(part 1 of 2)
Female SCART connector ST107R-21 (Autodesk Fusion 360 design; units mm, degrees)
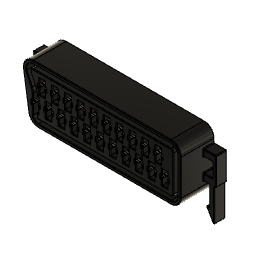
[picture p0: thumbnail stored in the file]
sketch "Sketch1" plane through (0, 0, 0) normal (0, 1, 0) x axis (1, 0, 0)
  line L1 (47.1, 0) -> (0, 0)
  line L2 (47.1, -16.5) -> (47.1, 0)
  line L3 (0, -16.5) -> (47.1, -16.5)
  line L4 (0, 0) -> (0, -16.5)
  line L5 (0, -8.25) -> (47.1, -8.25)
  line L6 (0, -5.71) -> (47.1, -5.71)
  line L7 (0, -10.79) -> (47.1, -10.79)
  line L8 (23.3, -16.5) -> (23.3, 0)
  line L9 (24.1, -7.81) -> (22.5, -7.81)
  line L10 (24.1, -3.61) -> (24.1, -7.81)
  line L11 (22.5, -3.61) -> (24.1, -3.61)
  line L12 (22.5, -7.81) -> (22.5, -3.61)
  line L13 (3.45, -3.61) -> (5.05, -3.61)
  line L14 (5.05, -3.61) -> (5.05, -7.81)
  line L15 (3.45, -7.81) -> (3.45, -3.61)
  line L16 (5.05, -7.81) -> (3.45, -7.81)
  line L17 (7.26, -3.61) -> (8.86, -3.61)
  line L18 (8.86, -3.61) -> (8.86, -7.81)
  line L19 (7.26, -7.81) -> (7.26, -3.61)
  line L20 (8.86, -7.81) -> (7.26, -7.81)
  line L21 (11.07, -3.61) -> (12.67, -3.61)
  line L22 (12.67, -3.61) -> (12.67, -7.81)
  line L23 (11.07, -7.81) -> (11.07, -3.61)
  line L24 (12.67, -7.81) -> (11.07, -7.81)
  line L25 (14.88, -3.61) -> (16.48, -3.61)
  line L26 (16.48, -3.61) -> (16.48, -7.81)
  line L27 (14.88, -7.81) -> (14.88, -3.61)
  line L28 (16.48, -7.81) -> (14.88, -7.81)
  line L29 (18.69, -3.61) -> (20.29, -3.61)
  line L30 (20.29, -3.61) -> (20.29, -7.81)
  line L31 (18.69, -7.81) -> (18.69, -3.61)
  line L32 (20.29, -7.81) -> (18.69, -7.81)
  line L33 (26.31, -3.61) -> (27.91, -3.61)
  line L34 (27.91, -3.61) -> (27.91, -7.81)
  line L35 (26.31, -7.81) -> (26.31, -3.61)
  line L36 (27.91, -7.81) -> (26.31, -7.81)
  line L37 (30.12, -3.61) -> (31.72, -3.61)
  line L38 (31.72, -3.61) -> (31.72, -7.81)
  line L39 (30.12, -7.81) -> (30.12, -3.61)
  line L40 (31.72, -7.81) -> (30.12, -7.81)
  line L41 (33.93, -3.61) -> (35.53, -3.61)
  line L42 (35.53, -3.61) -> (35.53, -7.81)
  line L43 (33.93, -7.81) -> (33.93, -3.61)
  line L44 (35.53, -7.81) -> (33.93, -7.81)
  line L45 (37.74, -3.61) -> (39.34, -3.61)
  line L46 (39.34, -3.61) -> (39.34, -7.81)
  line L47 (37.74, -7.81) -> (37.74, -3.61)
  line L48 (39.34, -7.81) -> (37.74, -7.81)
  line L49 (41.55, -3.61) -> (43.15, -3.61)
  line L50 (43.15, -3.61) -> (43.15, -7.81)
  line L51 (41.55, -7.81) -> (41.55, -3.61)
  line L52 (43.15, -7.81) -> (41.55, -7.81)
  line L53 (41.55, -7.81) -> (39.34, -7.81)
  line L54 (40.445, -14) -> (40.445, -7.81)
  line L55 (41.245, -12.89) -> (39.645, -12.89)
  line L56 (41.245, -8.69) -> (41.245, -12.89)
  line L57 (39.645, -8.69) -> (41.245, -8.69)
  line L58 (39.645, -12.89) -> (39.645, -8.69)
  line L59 (37.435, -8.69) -> (37.435, -12.89)
  line L60 (35.835, -8.69) -> (37.435, -8.69)
  line L61 (35.835, -12.89) -> (35.835, -8.69)
  line L62 (37.435, -12.89) -> (35.835, -12.89)
  line L63 (33.625, -8.69) -> (33.625, -12.89)
  line L64 (32.025, -8.69) -> (33.625, -8.69)
  line L65 (32.025, -12.89) -> (32.025, -8.69)
  line L66 (33.625, -12.89) -> (32.025, -12.89)
  line L67 (29.815, -8.69) -> (29.815, -12.89)
  line L68 (28.215, -8.69) -> (29.815, -8.69)
  line L69 (28.215, -12.89) -> (28.215, -8.69)
  line L70 (29.815, -12.89) -> (28.215, -12.89)
  line L71 (26.005, -8.69) -> (26.005, -12.89)
  line L72 (24.405, -8.69) -> (26.005, -8.69)
  line L73 (24.405, -12.89) -> (24.405, -8.69)
  line L74 (26.005, -12.89) -> (24.405, -12.89)
  line L75 (22.195, -8.69) -> (22.195, -12.89)
  line L76 (20.595, -8.69) -> (22.195, -8.69)
  line L77 (20.595, -12.89) -> (20.595, -8.69)
  line L78 (22.195, -12.89) -> (20.595, -12.89)
  line L79 (18.385, -8.69) -> (18.385, -12.89)
  line L80 (16.785, -8.69) -> (18.385, -8.69)
  line L81 (16.785, -12.89) -> (16.785, -8.69)
  line L82 (18.385, -12.89) -> (16.785, -12.89)
  line L83 (14.575, -8.69) -> (14.575, -12.89)
  line L84 (12.975, -8.69) -> (14.575, -8.69)
  line L85 (12.975, -12.89) -> (12.975, -8.69)
  line L86 (14.575, -12.89) -> (12.975, -12.89)
  line L87 (10.765, -8.69) -> (10.765, -12.89)
  line L88 (9.165, -8.69) -> (10.765, -8.69)
  line L89 (9.165, -12.89) -> (9.165, -8.69)
  line L90 (10.765, -12.89) -> (9.165, -12.89)
  line L91 (6.955, -8.69) -> (6.955, -12.89)
  line L92 (5.355, -8.69) -> (6.955, -8.69)
  line L93 (5.355, -12.89) -> (5.355, -8.69)
  line L94 (6.955, -12.89) -> (5.355, -12.89)
  line L95 (2.5, 0) -> (0, -16.5)
  line L96 (24.5, -6.21) -> (22.1, -6.21)
  line L97 (24.5, -5.21) -> (24.5, -6.21)
  line L98 (22.1, -5.21) -> (24.5, -5.21)
  line L99 (22.1, -6.21) -> (22.1, -5.21)
  line L100 (3.05, -5.21) -> (5.45, -5.21)
  line L101 (5.45, -5.21) -> (5.45, -6.21)
  line L102 (5.45, -6.21) -> (3.05, -6.21)
  line L103 (3.05, -6.21) -> (3.05, -5.21)
  line L104 (6.86, -5.21) -> (9.26, -5.21)
  line L105 (9.26, -5.21) -> (9.26, -6.21)
  line L106 (9.26, -6.21) -> (6.86, -6.21)
  line L107 (6.86, -6.21) -> (6.86, -5.21)
  line L108 (10.67, -5.21) -> (13.07, -5.21)
  line L109 (13.07, -5.21) -> (13.07, -6.21)
  line L110 (13.07, -6.21) -> (10.67, -6.21)
  line L111 (10.67, -6.21) -> (10.67, -5.21)
  line L112 (14.48, -5.21) -> (16.88, -5.21)
  line L113 (16.88, -5.21) -> (16.88, -6.21)
  line L114 (16.88, -6.21) -> (14.48, -6.21)
  line L115 (14.48, -6.21) -> (14.48, -5.21)
  line L116 (18.29, -5.21) -> (20.69, -5.21)
  line L117 (20.69, -5.21) -> (20.69, -6.21)
  line L118 (20.69, -6.21) -> (18.29, -6.21)
  line L119 (18.29, -6.21) -> (18.29, -5.21)
  line L120 (25.91, -5.21) -> (28.31, -5.21)
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  point P1 (0, 0)
  point P2 (0, 0)
  point P6 (47.1, -8.25)
  point P7 (0, -8.25)
  point P58 (40.445, -7.81)
  point P100 (2.5, 0)
  point P3 (47.1, 0)
  point P5 (0, -16.5)
  point P14 (22.5, -7.81)
  point P15 (24.1, -7.81)
  point P17 (22.5, -3.61)
  point P61 (41.245, -12.89)
  point P62 (41.245, -8.69)
  point P60 (39.645, -12.89)
  point P102 (24.5, -6.21)
  point P103 (24.5, -5.21)
  point P101 (22.1, -6.21)
  point P145 (39.245, -11.29)
  point P146 (41.645, -11.29)
  point P148 (39.245, -10.29)
  horizontal L1
  vertical L2
  horizontal L3
  vertical L4
  coincident P1 P2
  midpoint L2 P6
  midpoint L4 P7
  parallel L5 L6
  parallel L5 L7
  symmetric L5 L6 L7
  horizontal L9
  vertical L10
  horizontal L11
  vertical L12
  symmetric L6 L9 L11
  symmetric L8 L10 L12
  midpoint L53 P58
  perpendicular L7 L54
  horizontal L55
  vertical L56
  horizontal L57
  vertical L58
  symmetric L54 L56 L58
  symmetric L7 L55 L57
  coincident L1 P100
  horizontal L96
  vertical L97
  horizontal L98
  vertical L99
  symmetric L8 L97 L99
  symmetric L6 L96 L98
  dimension "d15" distance P2 P3 = 47.1 (= "23.3 mm + 23.8 mm")
  dimension "d16" distance P2 P5 = 16.5
  dimension "d19" distance L6 L7 = 5.08
  dimension "d20" = 23.8
  dimension "d21" distance P14 P15 = 1.6
  dimension "d22" distance P14 P17 = 4.2
  dimension "d27" distance P61 P62 = 4.2
  dimension "d28" distance P60 P61 = 1.6
  dimension "d36" distance P102 P103 = 1
  dimension "d37" distance P101 P102 = 2.4
  dimension "d38" distance P145 P146 = 2.4
  dimension "d39" distance P145 P148 = 1
  dimension "d25" R-Pattern1-uDistance = 3.81
  dimension "d26" R-Pattern1-vDistance = 0
  dimension "d31" R-Pattern2-uDistance = -3.81
  dimension "d32" R-Pattern2-vDistance = 0
extrude "Extrude4" new body sketch "Sketch1" along normal blind 10
fillet "Fillet3" radius 3
sketch "Sketch4" plane through (0, 0, 0) normal (0, -1, 0) x axis (1, 0, 0)
  line L1 (26.405, 10.29) -> (26.405, 11.29)
  line L2 (26.005, 10.29) -> (26.405, 10.29)
  line L3 (26.005, 8.69) -> (26.005, 10.29)
  line L4 (24.405, 8.69) -> (26.005, 8.69)
  line L5 (24.405, 10.29) -> (24.405, 8.69)
  line L6 (24.005, 10.29) -> (24.405, 10.29)
  line L7 (24.005, 11.29) -> (24.005, 10.29)
  line L8 (24.405, 11.29) -> (24.005, 11.29)
  line L9 (24.405, 12.89) -> (24.405, 11.29)
  line L10 (26.005, 12.89) -> (24.405, 12.89)
  line L11 (26.005, 11.29) -> (26.005, 12.89)
  line L12 (26.405, 11.29) -> (26.005, 11.29)
  line L13 (22.595, 10.29) -> (22.595, 11.29)
  line L14 (22.195, 10.29) -> (22.595, 10.29)
  line L15 (22.195, 8.69) -> (22.195, 10.29)
  line L16 (20.595, 8.69) -> (22.195, 8.69)
  line L17 (20.595, 10.29) -> (20.595, 8.69)
  line L18 (20.195, 10.29) -> (20.595, 10.29)
  line L19 (20.195, 11.29) -> (20.195, 10.29)
  line L20 (20.595, 11.29) -> (20.195, 11.29)
  line L21 (20.595, 12.89) -> (20.595, 11.29)
  line L22 (22.195, 12.89) -> (20.595, 12.89)
  line L23 (22.195, 11.29) -> (22.195, 12.89)
  line L24 (22.595, 11.29) -> (22.195, 11.29)
  line L25 (11.165, 10.29) -> (11.165, 11.29)
  line L26 (10.765, 10.29) -> (11.165, 10.29)
  line L27 (10.765, 8.69) -> (10.765, 10.29)
  line L28 (9.165, 8.69) -> (10.765, 8.69)
  line L29 (9.165, 10.29) -> (9.165, 8.69)
  line L30 (8.765, 10.29) -> (9.165, 10.29)
  line L31 (8.765, 11.29) -> (8.765, 10.29)
  line L32 (9.165, 11.29) -> (8.765, 11.29)
  line L33 (9.165, 12.89) -> (9.165, 11.29)
  line L34 (10.765, 12.89) -> (9.165, 12.89)
  line L35 (10.765, 11.29) -> (10.765, 12.89)
  line L36 (11.165, 11.29) -> (10.765, 11.29)
  line L37 (39.245, 11.29) -> (39.245, 10.29)
  line L38 (39.645, 11.29) -> (39.245, 11.29)
  line L39 (39.645, 12.89) -> (39.645, 11.29)
  line L40 (41.245, 12.89) -> (39.645, 12.89)
  line L41 (41.245, 11.29) -> (41.245, 12.89)
  line L42 (41.645, 11.29) -> (41.245, 11.29)
  line L43 (41.645, 10.29) -> (41.645, 11.29)
  line L44 (41.245, 10.29) -> (41.645, 10.29)
  line L45 (41.245, 8.69) -> (41.245, 10.29)
  line L46 (39.645, 8.69) -> (41.245, 8.69)
  line L47 (39.645, 10.29) -> (39.645, 8.69)
  line L48 (39.245, 10.29) -> (39.645, 10.29)
  line L49 (37.34, 6.21) -> (37.34, 5.21)
  line L50 (37.74, 6.21) -> (37.34, 6.21)
  line L51 (37.74, 7.81) -> (37.74, 6.21)
  line L52 (39.34, 7.81) -> (37.74, 7.81)
  line L53 (39.34, 6.21) -> (39.34, 7.81)
  line L54 (39.74, 6.21) -> (39.34, 6.21)
  line L55 (39.74, 5.21) -> (39.74, 6.21)
  line L56 (39.34, 5.21) -> (39.74, 5.21)
  line L57 (39.34, 3.61) -> (39.34, 5.21)
  line L58 (37.74, 3.61) -> (39.34, 3.61)
  line L59 (37.74, 5.21) -> (37.74, 3.61)
  line L60 (37.34, 5.21) -> (37.74, 5.21)
  line L61 (3.05, 6.21) -> (3.05, 5.21)
  line L62 (3.45, 6.21) -> (3.05, 6.21)
  line L63 (3.45, 7.81) -> (3.45, 6.21)
  line L64 (5.05, 7.81) -> (3.45, 7.81)
  line L65 (5.05, 6.21) -> (5.05, 7.81)
  line L66 (5.45, 6.21) -> (5.05, 6.21)
  line L67 (5.45, 5.21) -> (5.45, 6.21)
  line L68 (5.05, 5.21) -> (5.45, 5.21)
  line L69 (5.05, 3.61) -> (5.05, 5.21)
  line L70 (3.45, 3.61) -> (5.05, 3.61)
  line L71 (3.45, 5.21) -> (3.45, 3.61)
  line L72 (3.05, 5.21) -> (3.45, 5.21)
  line L73 (6.86, 6.21) -> (6.86, 5.21)
  line L74 (7.26, 6.21) -> (6.86, 6.21)
  line L75 (7.26, 7.81) -> (7.26, 6.21)
  line L76 (8.86, 7.81) -> (7.26, 7.81)
  line L77 (8.86, 6.21) -> (8.86, 7.81)
  line L78 (9.26, 6.21) -> (8.86, 6.21)
  line L79 (9.26, 5.21) -> (9.26, 6.21)
  line L80 (8.86, 5.21) -> (9.26, 5.21)
  line L81 (8.86, 3.61) -> (8.86, 5.21)
  line L82 (7.26, 3.61) -> (8.86, 3.61)
  line L83 (7.26, 5.21) -> (7.26, 3.61)
  line L84 (6.86, 5.21) -> (7.26, 5.21)
  line L85 (10.67, 6.21) -> (10.67, 5.21)
  line L86 (11.07, 6.21) -> (10.67, 6.21)
  line L87 (11.07, 7.81) -> (11.07, 6.21)
  line L88 (12.67, 7.81) -> (11.07, 7.81)
  line L89 (12.67, 6.21) -> (12.67, 7.81)
  line L90 (13.07, 6.21) -> (12.67, 6.21)
  line L91 (13.07, 5.21) -> (13.07, 6.21)
  line L92 (12.67, 5.21) -> (13.07, 5.21)
  line L93 (12.67, 3.61) -> (12.67, 5.21)
  line L94 (11.07, 3.61) -> (12.67, 3.61)
  line L95 (11.07, 5.21) -> (11.07, 3.61)
  line L96 (10.67, 5.21) -> (11.07, 5.21)
  line L97 (30.215, 10.29) -> (30.215, 11.29)
  line L98 (29.815, 10.29) -> (30.215, 10.29)
  line L99 (29.815, 8.69) -> (29.815, 10.29)
  line L100 (28.215, 8.69) -> (29.815, 8.69)
  line L101 (28.215, 10.29) -> (28.215, 8.69)
  line L102 (27.815, 10.29) -> (28.215, 10.29)
  line L103 (27.815, 11.29) -> (27.815, 10.29)
  line L104 (28.215, 11.29) -> (27.815, 11.29)
  line L105 (28.215, 12.89) -> (28.215, 11.29)
  line L106 (29.815, 12.89) -> (28.215, 12.89)
  line L107 (29.815, 11.29) -> (29.815, 12.89)
  line L108 (30.215, 11.29) -> (29.815, 11.29)
  line L109 (18.785, 10.29) -> (18.785, 11.29)
  line L110 (18.385, 10.29) -> (18.785, 10.29)
  line L111 (18.385, 8.69) -> (18.385, 10.29)
  line L112 (16.785, 8.69) -> (18.385, 8.69)
  line L113 (16.785, 10.29) -> (16.785, 8.69)
  line L114 (16.385, 10.29) -> (16.785, 10.29)
  line L115 (16.385, 11.29) -> (16.385, 10.29)
  line L116 (16.785, 11.29) -> (16.385, 11.29)
  line L117 (16.785, 12.89) -> (16.785, 11.29)
  line L118 (18.385, 12.89) -> (16.785, 12.89)
  line L119 (18.385, 11.29) -> (18.385, 12.89)
  line L120 (18.785, 11.29) -> (18.385, 11.29)
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  point P72 (3.45, 3.61)
  point P275 (3.45, 3.61)
  point P65 (3.45, 7.81)
  point P279 (3.45, 7.81)
  point P280 (3.45, 8.81)
  coincident P72 P275
  coincident P65 P279
  dimension "d41" radius = 1.5
  dimension "d42" distance P279 P280 = 1
  dimension "d43" radius = 3.5
  dimension "d44" = -1.2
extrude "Extrude5" cut sketch "Sketch4" against normal blind 8
sketch "Sketch5" plane through (0, 10, 0) normal (0, 1, 0) x axis (-1, 0, 0)
  line L1 (-0.5226, 13.0506) -> (-2.1135, 2.5506)
  line L2 (-44.1, 16.5) -> (-3.4888, 16.5)
  line L3 (-47.1, 3) -> (-47.1, 13.5)
  line L4 (-5.0797, 0) -> (-44.1, 0)
  line L5 (-26.405, 11.29) -> (-26.405, 10.29)
  line L6 (-26.005, 11.29) -> (-26.405, 11.29)
  line L7 (-26.005, 12.89) -> (-26.005, 11.29)
  line L8 (-24.405, 12.89) -> (-26.005, 12.89)
  line L9 (-24.405, 11.29) -> (-24.405, 12.89)
  line L10 (-24.005, 11.29) -> (-24.405, 11.29)
  line L11 (-24.005, 10.29) -> (-24.005, 11.29)
  line L12 (-24.405, 10.29) -> (-24.005, 10.29)
  line L13 (-24.405, 8.69) -> (-24.405, 10.29)
  line L14 (-26.005, 8.69) -> (-24.405, 8.69)
  line L15 (-26.005, 10.29) -> (-26.005, 8.69)
  line L16 (-26.405, 10.29) -> (-26.005, 10.29)
  line L17 (-22.595, 11.29) -> (-22.595, 10.29)
  line L18 (-22.195, 11.29) -> (-22.595, 11.29)
  line L19 (-22.195, 12.89) -> (-22.195, 11.29)
  line L20 (-20.595, 12.89) -> (-22.195, 12.89)
  line L21 (-20.595, 11.29) -> (-20.595, 12.89)
  line L22 (-20.195, 11.29) -> (-20.595, 11.29)
  line L23 (-20.195, 10.29) -> (-20.195, 11.29)
  line L24 (-20.595, 10.29) -> (-20.195, 10.29)
  line L25 (-20.595, 8.69) -> (-20.595, 10.29)
  line L26 (-22.195, 8.69) -> (-20.595, 8.69)
  line L27 (-22.195, 10.29) -> (-22.195, 8.69)
  line L28 (-22.595, 10.29) -> (-22.195, 10.29)
  line L29 (-11.165, 11.29) -> (-11.165, 10.29)
  line L30 (-10.765, 11.29) -> (-11.165, 11.29)
  line L31 (-10.765, 12.89) -> (-10.765, 11.29)
  line L32 (-9.165, 12.89) -> (-10.765, 12.89)
  line L33 (-9.165, 11.29) -> (-9.165, 12.89)
  line L34 (-8.765, 11.29) -> (-9.165, 11.29)
  line L35 (-8.765, 10.29) -> (-8.765, 11.29)
  line L36 (-9.165, 10.29) -> (-8.765, 10.29)
  line L37 (-9.165, 8.69) -> (-9.165, 10.29)
  line L38 (-10.765, 8.69) -> (-9.165, 8.69)
  line L39 (-10.765, 10.29) -> (-10.765, 8.69)
  line L40 (-11.165, 10.29) -> (-10.765, 10.29)
  line L41 (-39.245, 10.29) -> (-39.245, 11.29)
  line L42 (-39.645, 10.29) -> (-39.245, 10.29)
  line L43 (-39.645, 8.69) -> (-39.645, 10.29)
  line L44 (-41.245, 8.69) -> (-39.645, 8.69)
  line L45 (-41.245, 10.29) -> (-41.245, 8.69)
  line L46 (-41.645, 10.29) -> (-41.245, 10.29)
  line L47 (-41.645, 11.29) -> (-41.645, 10.29)
  line L48 (-41.245, 11.29) -> (-41.645, 11.29)
  line L49 (-41.245, 12.89) -> (-41.245, 11.29)
  line L50 (-39.645, 12.89) -> (-41.245, 12.89)
  line L51 (-39.645, 11.29) -> (-39.645, 12.89)
  line L52 (-39.245, 11.29) -> (-39.645, 11.29)
  line L53 (-37.34, 5.21) -> (-37.34, 6.21)
  line L54 (-37.74, 5.21) -> (-37.34, 5.21)
  line L55 (-37.74, 3.61) -> (-37.74, 5.21)
  line L56 (-39.34, 3.61) -> (-37.74, 3.61)
  line L57 (-39.34, 5.21) -> (-39.34, 3.61)
  line L58 (-39.74, 5.21) -> (-39.34, 5.21)
  line L59 (-39.74, 6.21) -> (-39.74, 5.21)
  line L60 (-39.34, 6.21) -> (-39.74, 6.21)
  line L61 (-39.34, 7.81) -> (-39.34, 6.21)
  line L62 (-37.74, 7.81) -> (-39.34, 7.81)
  line L63 (-37.74, 6.21) -> (-37.74, 7.81)
  line L64 (-37.34, 6.21) -> (-37.74, 6.21)
  line L65 (-3.05, 5.21) -> (-3.05, 6.21)
  line L66 (-3.45, 5.21) -> (-3.05, 5.21)
  line L67 (-3.45, 3.61) -> (-3.45, 5.21)
  line L68 (-5.05, 3.61) -> (-3.45, 3.61)
  line L69 (-5.05, 5.21) -> (-5.05, 3.61)
  line L70 (-5.45, 5.21) -> (-5.05, 5.21)
  line L71 (-5.45, 6.21) -> (-5.45, 5.21)
  line L72 (-5.05, 6.21) -> (-5.45, 6.21)
  line L73 (-5.05, 7.81) -> (-5.05, 6.21)
  line L74 (-3.45, 7.81) -> (-5.05, 7.81)
  line L75 (-3.45, 6.21) -> (-3.45, 7.81)
  line L76 (-3.05, 6.21) -> (-3.45, 6.21)
  line L77 (-6.86, 5.21) -> (-6.86, 6.21)
  line L78 (-7.26, 5.21) -> (-6.86, 5.21)
  line L79 (-7.26, 3.61) -> (-7.26, 5.21)
  line L80 (-8.86, 3.61) -> (-7.26, 3.61)
  line L81 (-8.86, 5.21) -> (-8.86, 3.61)
  line L82 (-9.26, 5.21) -> (-8.86, 5.21)
  line L83 (-9.26, 6.21) -> (-9.26, 5.21)
  line L84 (-8.86, 6.21) -> (-9.26, 6.21)
  line L85 (-8.86, 7.81) -> (-8.86, 6.21)
  line L86 (-7.26, 7.81) -> (-8.86, 7.81)
  line L87 (-7.26, 6.21) -> (-7.26, 7.81)
  line L88 (-6.86, 6.21) -> (-7.26, 6.21)
  line L89 (-10.67, 5.21) -> (-10.67, 6.21)
  line L90 (-11.07, 5.21) -> (-10.67, 5.21)
  line L91 (-11.07, 3.61) -> (-11.07, 5.21)
  line L92 (-12.67, 3.61) -> (-11.07, 3.61)
  line L93 (-12.67, 5.21) -> (-12.67, 3.61)
  line L94 (-13.07, 5.21) -> (-12.67, 5.21)
  line L95 (-13.07, 6.21) -> (-13.07, 5.21)
  line L96 (-12.67, 6.21) -> (-13.07, 6.21)
  line L97 (-12.67, 7.81) -> (-12.67, 6.21)
  line L98 (-11.07, 7.81) -> (-12.67, 7.81)
  line L99 (-11.07, 6.21) -> (-11.07, 7.81)
  line L100 (-10.67, 6.21) -> (-11.07, 6.21)
  line L101 (-30.215, 11.29) -> (-30.215, 10.29)
  line L102 (-29.815, 11.29) -> (-30.215, 11.29)
  line L103 (-29.815, 12.89) -> (-29.815, 11.29)
  line L104 (-28.215, 12.89) -> (-29.815, 12.89)
  line L105 (-28.215, 11.29) -> (-28.215, 12.89)
  line L106 (-27.815, 11.29) -> (-28.215, 11.29)
  line L107 (-27.815, 10.29) -> (-27.815, 11.29)
  line L108 (-28.215, 10.29) -> (-27.815, 10.29)
  line L109 (-28.215, 8.69) -> (-28.215, 10.29)
  line L110 (-29.815, 8.69) -> (-28.215, 8.69)
  line L111 (-29.815, 10.29) -> (-29.815, 8.69)
  line L112 (-30.215, 10.29) -> (-29.815, 10.29)
  line L113 (-18.785, 11.29) -> (-18.785, 10.29)
  line L114 (-18.385, 11.29) -> (-18.785, 11.29)
  line L115 (-18.385, 12.89) -> (-18.385, 11.29)
  line L116 (-16.785, 12.89) -> (-18.385, 12.89)
  line L117 (-16.785, 11.29) -> (-16.785, 12.89)
  line L118 (-16.385, 11.29) -> (-16.785, 11.29)
  line L119 (-16.385, 10.29) -> (-16.385, 11.29)
  line L120 (-16.785, 10.29) -> (-16.385, 10.29)
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  point P57 (-41.645, 11.29)
  point P266 (-41.645, 11.29)
  point P236 (-4.955, 11.29)
  point P267 (-4.955, 11.29)
  point P56 (-41.645, 10.29)
  point P268 (-41.645, 10.29)
  point P237 (-4.955, 10.29)
  point P269 (-4.955, 10.29)
  point P201 (-43.55, 6.21)
  point P270 (-43.55, 6.21)
  point P74 (-3.05, 6.21)
  point P271 (-3.05, 6.21)
  point P200 (-43.55, 5.21)
  point P272 (-43.55, 5.21)
  point P75 (-3.05, 5.21)
  point P273 (-3.05, 5.21)
  coincident P57 P266
  coincident P236 P267
  coincident P56 P268
  coincident P237 P269
  coincident P201 P270
  coincident P74 P271
  coincident P200 P272
  coincident P75 P273
extrude "Extrude6" add sketch "Sketch5" against normal blind 2
sketch "Sketch7" plane through (0, 10, 0) normal (0, 1, 0) x axis (-1, 0, 0)
  line L1 (-0.5226, 13.0506) -> (-2.1135, 2.5506)
  line L2 (-44.1, 16.5) -> (-3.4888, 16.5)
  line L3 (-47.1, 3) -> (-47.1, 13.5)
  line L4 (-5.0797, 0) -> (-44.1, 0)
  line L5 (-26.405, 11.29) -> (-26.405, 10.29)
  line L6 (-24.005, 11.29) -> (-26.405, 11.29)
  line L7 (-24.005, 10.29) -> (-24.005, 11.29)
  line L8 (-26.405, 10.29) -> (-24.005, 10.29)
  line L9 (-22.595, 11.29) -> (-22.595, 10.29)
  line L10 (-20.195, 11.29) -> (-22.595, 11.29)
  line L11 (-20.195, 10.29) -> (-20.195, 11.29)
  line L12 (-22.595, 10.29) -> (-20.195, 10.29)
  line L13 (-11.165, 11.29) -> (-11.165, 10.29)
  line L14 (-8.765, 11.29) -> (-11.165, 11.29)
  line L15 (-8.765, 10.29) -> (-8.765, 11.29)
  line L16 (-11.165, 10.29) -> (-8.765, 10.29)
  line L17 (-39.245, 10.29) -> (-39.245, 11.29)
  line L18 (-41.645, 10.29) -> (-39.245, 10.29)
  line L19 (-41.645, 11.29) -> (-41.645, 10.29)
  line L20 (-39.245, 11.29) -> (-41.645, 11.29)
  line L21 (-37.34, 5.21) -> (-37.34, 6.21)
  line L22 (-39.74, 5.21) -> (-37.34, 5.21)
  line L23 (-39.74, 6.21) -> (-39.74, 5.21)
  line L24 (-37.34, 6.21) -> (-39.74, 6.21)
  line L25 (-3.05, 5.21) -> (-3.05, 6.21)
  line L26 (-5.45, 5.21) -> (-3.05, 5.21)
  line L27 (-5.45, 6.21) -> (-5.45, 5.21)
  line L28 (-3.05, 6.21) -> (-5.45, 6.21)
  line L29 (-6.86, 5.21) -> (-6.86, 6.21)
  line L30 (-9.26, 5.21) -> (-6.86, 5.21)
  line L31 (-9.26, 6.21) -> (-9.26, 5.21)
  line L32 (-6.86, 6.21) -> (-9.26, 6.21)
  line L33 (-10.67, 5.21) -> (-10.67, 6.21)
  line L34 (-13.07, 5.21) -> (-10.67, 5.21)
  line L35 (-13.07, 6.21) -> (-13.07, 5.21)
  line L36 (-10.67, 6.21) -> (-13.07, 6.21)
  line L37 (-30.215, 11.29) -> (-30.215, 10.29)
  line L38 (-27.815, 11.29) -> (-30.215, 11.29)
  line L39 (-27.815, 10.29) -> (-27.815, 11.29)
  line L40 (-30.215, 10.29) -> (-27.815, 10.29)
  line L41 (-18.785, 11.29) -> (-18.785, 10.29)
  line L42 (-16.385, 11.29) -> (-18.785, 11.29)
  line L43 (-16.385, 10.29) -> (-16.385, 11.29)
  line L44 (-18.785, 10.29) -> (-16.385, 10.29)
  line L45 (-14.975, 11.29) -> (-14.975, 10.29)
  line L46 (-12.575, 11.29) -> (-14.975, 11.29)
  line L47 (-12.575, 10.29) -> (-12.575, 11.29)
  line L48 (-14.975, 10.29) -> (-12.575, 10.29)
  line L49 (-34.025, 11.29) -> (-34.025, 10.29)
  line L50 (-31.625, 11.29) -> (-34.025, 11.29)
  line L51 (-31.625, 10.29) -> (-31.625, 11.29)
  line L52 (-34.025, 10.29) -> (-31.625, 10.29)
  line L53 (-25.91, 5.21) -> (-25.91, 6.21)
  line L54 (-28.31, 5.21) -> (-25.91, 5.21)
  line L55 (-28.31, 6.21) -> (-28.31, 5.21)
  line L56 (-25.91, 6.21) -> (-28.31, 6.21)
  line L57 (-18.29, 5.21) -> (-18.29, 6.21)
  line L58 (-20.69, 5.21) -> (-18.29, 5.21)
  line L59 (-20.69, 6.21) -> (-20.69, 5.21)
  line L60 (-18.29, 6.21) -> (-20.69, 6.21)
  line L61 (-33.53, 5.21) -> (-33.53, 6.21)
  line L62 (-35.93, 5.21) -> (-33.53, 5.21)
  line L63 (-35.93, 6.21) -> (-35.93, 5.21)
  line L64 (-33.53, 6.21) -> (-35.93, 6.21)
  line L65 (-41.15, 5.21) -> (-41.15, 6.21)
  line L66 (-43.55, 5.21) -> (-41.15, 5.21)
  line L67 (-43.55, 6.21) -> (-43.55, 5.21)
  line L68 (-41.15, 6.21) -> (-43.55, 6.21)
  line L69 (-14.48, 5.21) -> (-14.48, 6.21)
  line L70 (-16.88, 5.21) -> (-14.48, 5.21)
  line L71 (-16.88, 6.21) -> (-16.88, 5.21)
  line L72 (-14.48, 6.21) -> (-16.88, 6.21)
  line L73 (-37.835, 11.29) -> (-37.835, 10.29)
  line L74 (-35.435, 11.29) -> (-37.835, 11.29)
  line L75 (-35.435, 10.29) -> (-35.435, 11.29)
  line L76 (-37.835, 10.29) -> (-35.435, 10.29)
  line L77 (-7.355, 11.29) -> (-7.355, 10.29)
  line L78 (-4.955, 11.29) -> (-7.355, 11.29)
  line L79 (-4.955, 10.29) -> (-4.955, 11.29)
  line L80 (-7.355, 10.29) -> (-4.955, 10.29)
  line L81 (-29.72, 5.21) -> (-29.72, 6.21)
  line L82 (-32.12, 5.21) -> (-29.72, 5.21)
  line L83 (-32.12, 6.21) -> (-32.12, 5.21)
  line L84 (-29.72, 6.21) -> (-32.12, 6.21)
  line L85 (-22.1, 5.21) -> (-22.1, 6.21)
  line L86 (-24.5, 5.21) -> (-22.1, 5.21)
  line L87 (-24.5, 6.21) -> (-24.5, 5.21)
  line L88 (-22.1, 6.21) -> (-24.5, 6.21)
  line L89 (-59, 8.25) -> (-47.1, 8.25)
  line L90 (6.5921, 8.25) -> (-47.1, 8.25)
  line L91 (-50.7944, 12.35) -> (-47.1, 12.35)
  line L92 (-50.7944, 4.15) -> (-50.7944, 12.35)
  line L93 (-47.1, 4.15) -> (-50.7944, 4.15)
  line L94 (3.2056, 12.35) -> (-0.6288, 12.35)
  line L95 (3.2056, 4.15) -> (3.2056, 12.35)
  line L96 (-1.8712, 4.15) -> (3.2056, 4.15)
  line L97 (-23.7944, 0) -> (-23.7944, 16.5)
  line L98 (-49.7944, 10.35) -> (-47.1, 10.35)
  line L99 (-49.7944, 6.15) -> (-49.7944, 10.35)
  line L100 (-47.1, 6.15) -> (-49.7944, 6.15)
  line L101 (2.2056, 10.35) -> (-0.4884, 10.35)
  line L102 (2.2056, 6.15) -> (2.2056, 10.35)
  line L103 (-1.8712, 6.15) -> (2.2056, 6.15)
  line L104 (-0.4884, 6.15) -> (-0.4884, 10.35)
  line L105 (2.7056, -6) -> (2.7056, 4.15)
  line L106 (1.2056, 4.15) -> (1.2056, -1.7)
  line L107 (0.2056, -1.7) -> (2.7056, -6)
  line L108 (1.2056, -1.7) -> (0.2056, -1.7)
  line L109 (-50.2944, -6) -> (-50.2944, 4.15)
  line L110 (-47.7944, -1.7) -> (-50.2944, -6)
  line L111 (-48.7944, -1.7) -> (-47.7944, -1.7)
  line L112 (-48.7944, 4.15) -> (-48.7944, -1.7)
  arc A1 centre (-5.0797, 3) radius 3 clockwise from (-2.1135, 2.5506) to (-5.0797, 0)
  arc A2 centre (-3.4888, 13.5) radius 3 clockwise from (-3.4888, 16.5) to (-0.5226, 13.0506)
  arc A3 centre (-44.1, 13.5) radius 3 clockwise from (-47.1, 13.5) to (-44.1, 16.5)
  arc A4 centre (-44.1, 3) radius 3 clockwise from (-44.1, 0) to (-47.1, 3)
  point P98 (-47.1, 8.25)
  point P104 (-47.1, 4.15)
  point P105 (-0.6288, 12.35)
  point P108 (-1.8712, 4.15)
  point P109 (-23.7944, 16.5)
  point P110 (-23.7944, 0)
  point P119 (-0.4884, 6.15)
  point P120 (2.7056, 4.15)
  point P123 (1.2056, 4.15)
  point P125 (-50.2944, 4.15)
  point P129 (-48.7944, 4.15)
  point P102 (-50.7944, 12.35)
  point P103 (-50.7944, 4.15)
  point P106 (3.2056, 12.35)
  point P107 (3.2056, 4.15)
  point P121 (2.7056, -6)
  point P126 (-50.2944, -6)
  point P127 (-47.7944, -1.7)
  point P128 (-48.7944, -1.7)
  point P115 (-0.4884, 10.35)
  point P116 (2.2056, 10.35)
  point P12 (-44.1, 0)
  midpoint L3 P98
  perpendicular L3 L89
  horizontal L91
  perpendicular L91 L92
  coincident L3 P104
  perpendicular L3 L93
  coincident L1 P105
  perpendicular L79 L94
  perpendicular L26 L95
  coincident L1 P108
  perpendicular L25 L96
  midpoint L2 P109
  coincident L4 P110
  perpendicular L4 L97
  symmetric L92 L95 L97
  symmetric L89 L91 L93
  coincident L103 P119
  perpendicular L103 L104
  coincident L96 P120
  perpendicular L96 L105
  coincident L96 P123
  perpendicular L96 L106
  perpendicular L106 L108
  coincident L93 P125
  perpendicular L93 L109
  perpendicular L93 L112
  coincident L93 P129
  equal L106 L112
  equal L108 L111
  perpendicular L111 L112
  parallel L94 L101
  parallel L95 L102
  parallel L96 L103
  parallel L91 L98
  parallel L92 L99
  parallel L93 L100
  symmetric L97 L106 L112
  dimension "d50" distance L92 L95 = 54
  dimension "d51" distance P102 P103 = 8.2
  dimension "d52" distance P106 P107 = 8.2
  dimension "d55" distance L4 P121 = 6
  dimension "d57" distance L105 L106 = 1.5
  dimension "d59" distance L109 L112 = 1.5
  dimension "d60" distance L4 P126 = 6
  dimension "d61" distance P127 P128 = 1
  dimension "d65" distance L106 L112 = 50
  dimension "d67" distance L95 L102 = 1
  dimension "d68" distance L94 L101 = 2
  dimension "d69" distance L96 L103 = 2
  dimension "d70" distance L92 L99 = 1
  dimension "d71" distance L91 L98 = 2
  dimension "d72" distance L93 L100 = 2
  dimension "d73" distance P115 P116 = 2.694
  dimension "d175" distance P12 L111 = 1.7
extrude "Extrude7" add sketch "Sketch7" profile of L1 L3 L91 L92 L93 L94 L95 L96 L100 L99 L98 L102 L103 L101 L104 L105 L106 L107 L108 L109 L110 L111 L112 against normal blind 3.3
sketch "Sketch18" plane through (0, 10, 0) normal (0, 1, 0) x axis (-1, 0, 0)
  line L1 (2.2056, 10.35) -> (-0.4884, 10.35)
  line L2 (2.2056, 6.15) -> (2.2056, 10.35)
  line L3 (-0.4884, 6.15) -> (2.2056, 6.15)
  line L4 (-0.4884, 10.35) -> (-0.4884, 6.15)
  line L5 (-47.1, 3) -> (-47.1, 4.15)
  line L6 (-5.0797, 0) -> (-44.1, 0)
  line L7 (-1.8712, 4.15) -> (-2.1135, 2.5506)
  line L8 (1.2056, 4.15) -> (-1.8712, 4.15)
  line L9 (1.2056, -1.7) -> (1.2056, 4.15)
  line L10 (0.2056, -1.7) -> (1.2056, -1.7)
  line L11 (2.7056, -6) -> (0.2056, -1.7)
  line L12 (2.7056, 4.15) -> (2.7056, -6)
  line L13 (3.2056, 4.15) -> (2.7056, 4.15)
  line L14 (3.2056, 12.35) -> (3.2056, 4.15)
  line L15 (-0.6288, 12.35) -> (3.2056, 12.35)
  line L16 (-0.5226, 13.0506) -> (-0.6288, 12.35)
  line L17 (-44.1, 16.5) -> (-3.4888, 16.5)
  line L18 (-47.1, 12.35) -> (-47.1, 13.5)
  line L19 (-50.7944, 12.35) -> (-47.1, 12.35)
  line L20 (-50.7944, 4.15) -> (-50.7944, 12.35)
  line L21 (-50.2944, 4.15) -> (-50.7944, 4.15)
  line L22 (-50.2944, -6) -> (-50.2944, 4.15)
  line L23 (-47.7944, -1.7) -> (-50.2944, -6)
  line L24 (-48.7944, -1.7) -> (-47.7944, -1.7)
  line L25 (-48.7944, 4.15) -> (-48.7944, -1.7)
  line L26 (-47.1, 4.15) -> (-48.7944, 4.15)
  line L27 (-49.7944, 6.15) -> (-47.1, 6.15)
  line L28 (-49.7944, 10.35) -> (-49.7944, 6.15)
  line L29 (-47.1, 10.35) -> (-49.7944, 10.35)
  line L30 (-47.1, 6.15) -> (-47.1, 10.35)
  line L31 (-26.405, 11.29) -> (-26.405, 10.29)
  line L32 (-24.005, 11.29) -> (-26.405, 11.29)
  line L33 (-24.005, 10.29) -> (-24.005, 11.29)
  line L34 (-26.405, 10.29) -> (-24.005, 10.29)
  line L35 (-22.595, 11.29) -> (-22.595, 10.29)
  line L36 (-20.195, 11.29) -> (-22.595, 11.29)
  line L37 (-20.195, 10.29) -> (-20.195, 11.29)
  line L38 (-22.595, 10.29) -> (-20.195, 10.29)
  line L39 (-11.165, 11.29) -> (-11.165, 10.29)
  line L40 (-8.765, 11.29) -> (-11.165, 11.29)
  line L41 (-8.765, 10.29) -> (-8.765, 11.29)
  line L42 (-11.165, 10.29) -> (-8.765, 10.29)
  line L43 (-39.245, 10.29) -> (-39.245, 11.29)
  line L44 (-41.645, 10.29) -> (-39.245, 10.29)
  line L45 (-41.645, 11.29) -> (-41.645, 10.29)
  line L46 (-39.245, 11.29) -> (-41.645, 11.29)
  line L47 (-37.34, 5.21) -> (-37.34, 6.21)
  line L48 (-39.74, 5.21) -> (-37.34, 5.21)
  line L49 (-39.74, 6.21) -> (-39.74, 5.21)
  line L50 (-37.34, 6.21) -> (-39.74, 6.21)
  line L51 (-3.05, 5.21) -> (-3.05, 6.21)
  line L52 (-5.45, 5.21) -> (-3.05, 5.21)
  line L53 (-5.45, 6.21) -> (-5.45, 5.21)
  line L54 (-3.05, 6.21) -> (-5.45, 6.21)
  line L55 (-6.86, 5.21) -> (-6.86, 6.21)
  line L56 (-9.26, 5.21) -> (-6.86, 5.21)
  line L57 (-9.26, 6.21) -> (-9.26, 5.21)
  line L58 (-6.86, 6.21) -> (-9.26, 6.21)
  line L59 (-10.67, 5.21) -> (-10.67, 6.21)
  line L60 (-13.07, 5.21) -> (-10.67, 5.21)
  line L61 (-13.07, 6.21) -> (-13.07, 5.21)
  line L62 (-10.67, 6.21) -> (-13.07, 6.21)
  line L63 (-30.215, 11.29) -> (-30.215, 10.29)
  line L64 (-27.815, 11.29) -> (-30.215, 11.29)
  line L65 (-27.815, 10.29) -> (-27.815, 11.29)
  line L66 (-30.215, 10.29) -> (-27.815, 10.29)
  line L67 (-18.785, 11.29) -> (-18.785, 10.29)
  line L68 (-16.385, 11.29) -> (-18.785, 11.29)
  line L69 (-16.385, 10.29) -> (-16.385, 11.29)
  line L70 (-18.785, 10.29) -> (-16.385, 10.29)
  line L71 (-14.975, 11.29) -> (-14.975, 10.29)
  line L72 (-12.575, 11.29) -> (-14.975, 11.29)
  line L73 (-12.575, 10.29) -> (-12.575, 11.29)
  line L74 (-14.975, 10.29) -> (-12.575, 10.29)
  line L75 (-34.025, 11.29) -> (-34.025, 10.29)
  line L76 (-31.625, 11.29) -> (-34.025, 11.29)
  line L77 (-31.625, 10.29) -> (-31.625, 11.29)
  line L78 (-34.025, 10.29) -> (-31.625, 10.29)
  line L79 (-25.91, 5.21) -> (-25.91, 6.21)
  line L80 (-28.31, 5.21) -> (-25.91, 5.21)
  line L81 (-28.31, 6.21) -> (-28.31, 5.21)
  line L82 (-25.91, 6.21) -> (-28.31, 6.21)
  line L83 (-18.29, 5.21) -> (-18.29, 6.21)
  line L84 (-20.69, 5.21) -> (-18.29, 5.21)
  line L85 (-20.69, 6.21) -> (-20.69, 5.21)
  line L86 (-18.29, 6.21) -> (-20.69, 6.21)
  line L87 (-33.53, 5.21) -> (-33.53, 6.21)
  line L88 (-35.93, 5.21) -> (-33.53, 5.21)
  line L89 (-35.93, 6.21) -> (-35.93, 5.21)
  line L90 (-33.53, 6.21) -> (-35.93, 6.21)
  line L91 (-41.15, 5.21) -> (-41.15, 6.21)
  line L92 (-43.55, 5.21) -> (-41.15, 5.21)
  line L93 (-43.55, 6.21) -> (-43.55, 5.21)
  line L94 (-41.15, 6.21) -> (-43.55, 6.21)
  line L95 (-14.48, 5.21) -> (-14.48, 6.21)
  line L96 (-16.88, 5.21) -> (-14.48, 5.21)
  line L97 (-16.88, 6.21) -> (-16.88, 5.21)
  line L98 (-14.48, 6.21) -> (-16.88, 6.21)
  line L99 (-37.835, 11.29) -> (-37.835, 10.29)
  line L100 (-35.435, 11.29) -> (-37.835, 11.29)
  line L101 (-35.435, 10.29) -> (-35.435, 11.29)
  line L102 (-37.835, 10.29) -> (-35.435, 10.29)
  line L103 (-7.355, 11.29) -> (-7.355, 10.29)
  line L104 (-4.955, 11.29) -> (-7.355, 11.29)
  line L105 (-4.955, 10.29) -> (-4.955, 11.29)
  line L106 (-7.355, 10.29) -> (-4.955, 10.29)
  line L107 (-29.72, 5.21) -> (-29.72, 6.21)
  line L108 (-32.12, 5.21) -> (-29.72, 5.21)
  line L109 (-32.12, 6.21) -> (-32.12, 5.21)
  line L110 (-29.72, 6.21) -> (-32.12, 6.21)
  line L111 (-22.1, 5.21) -> (-22.1, 6.21)
  line L112 (-24.5, 5.21) -> (-22.1, 5.21)
  line L113 (-24.5, 6.21) -> (-24.5, 5.21)
  line L114 (-22.1, 6.21) -> (-24.5, 6.21)
  line L115 (-42.35, 0) -> (-42.35, 5.21)
  line L116 (-43.05, 0) -> (-43.05, 5.21)
  line L117 (-41.65, 0) -> (-41.65, 5.21)
  line L118 (-37.84, 0) -> (-37.84, 5.21)
  line L119 (-39.24, 0) -> (-39.24, 5.21)
  line L120 (-34.03, 0) -> (-34.03, 5.21)
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  point P124 (-42.35, 5.21)
  point P125 (-42.35, 0)
  point P10 (-5.0797, 0)
  point P170 (-5.0797, 0)
  midpoint L92 P124
  coincident L6 P125
  perpendicular L6 L115
  coincident P10 P170
  dimension "d118" = 0.7
  dimension "d119" = -0.7
  dimension "d122" R-Pattern1-uDistance = 3.81
  dimension "d123" R-Pattern1-vDistance = 0
extrude "Extrude14" add sketch "Sketch18" along normal blind 5.1
sketch "Sketch20" plane through (43.05, 0, 0) normal (1, 0, 0) x axis (0, 1, 0)
  line L1 (10, 0) -> (10, 5.21)
  line L2 (15.1, 0) -> (10, 0)
  line L3 (15.1, 5.21) -> (15.1, 0)
  line L4 (10, 5.21) -> (15.1, 5.21)
  line L5 (14.4, 5.21) -> (10, 5.21)
  line L6 (15.1, 2.3) -> (15.1, 4.51)
  arc A1 centre (14.4, 4.51) radius 0.7 clockwise from (14.4, 5.21) to (15.1, 4.51)
  point P2 (10, 5.21)
  point P6 (10, 5.21)
  point P7 (15.1, 2.3)
  coincident P2 P6
  coincident L3 P7
  perpendicular L4 L6
  tangent L5 A1
  tangent L6 A1
  dimension "d132" radius A1 = 0.7
fillet "Fillet9" radius 0.2
sketch "Sketch15" plane through (0, 10, 0) normal (0, 1, 0) x axis (-1, 0, 0)
  line L1 (2.2056, 10.35) -> (-0.4884, 10.35)
  line L2 (2.2056, 6.15) -> (2.2056, 10.35)
  line L3 (-0.4884, 6.15) -> (2.2056, 6.15)
  line L4 (-0.4884, 10.35) -> (-0.4884, 6.15)
  line L5 (-47.1, 3) -> (-47.1, 4.15)
  line L6 (-39.24, 0) -> (-41.65, 0)
  line L7 (-1.8712, 4.15) -> (-2.1135, 2.5506)
  line L8 (1.2056, 4.15) -> (-1.8712, 4.15)
  line L9 (1.2056, -1.7) -> (1.2056, 4.15)
  line L10 (0.2056, -1.7) -> (1.2056, -1.7)
  line L11 (2.7056, -6) -> (0.2056, -1.7)
  line L12 (2.7056, 4.15) -> (2.7056, -6)
  line L13 (3.2056, 4.15) -> (2.7056, 4.15)
  line L14 (3.2056, 12.35) -> (3.2056, 4.15)
  line L15 (-0.6288, 12.35) -> (3.2056, 12.35)
  line L16 (-0.5226, 13.0506) -> (-0.6288, 12.35)
  line L17 (-44.1, 16.5) -> (-3.4888, 16.5)
  line L18 (-47.1, 12.35) -> (-47.1, 13.5)
  line L19 (-50.7944, 12.35) -> (-47.1, 12.35)
  line L20 (-50.7944, 4.15) -> (-50.7944, 12.35)
  line L21 (-50.2944, 4.15) -> (-50.7944, 4.15)
  line L22 (-50.2944, -6) -> (-50.2944, 4.15)
  line L23 (-47.7944, -1.7) -> (-50.2944, -6)
  line L24 (-48.7944, -1.7) -> (-47.7944, -1.7)
  line L25 (-48.7944, 4.15) -> (-48.7944, -1.7)
  line L26 (-47.1, 4.15) -> (-48.7944, 4.15)
  line L27 (-49.7944, 6.15) -> (-47.1, 6.15)
  line L28 (-49.7944, 10.35) -> (-49.7944, 6.15)
  line L29 (-47.1, 10.35) -> (-49.7944, 10.35)
  line L30 (-47.1, 6.15) -> (-47.1, 10.35)
  line L31 (-26.405, 11.29) -> (-26.405, 10.29)
  line L32 (-24.005, 11.29) -> (-26.405, 11.29)
  line L33 (-24.005, 10.29) -> (-24.005, 11.29)
  line L34 (-26.405, 10.29) -> (-24.005, 10.29)
  line L35 (-22.595, 11.29) -> (-22.595, 10.29)
  line L36 (-20.195, 11.29) -> (-22.595, 11.29)
  line L37 (-20.195, 10.29) -> (-20.195, 11.29)
  line L38 (-22.595, 10.29) -> (-20.195, 10.29)
  line L39 (-11.165, 11.29) -> (-11.165, 10.29)
  line L40 (-8.765, 11.29) -> (-11.165, 11.29)
  line L41 (-8.765, 10.29) -> (-8.765, 11.29)
  line L42 (-11.165, 10.29) -> (-8.765, 10.29)
  line L43 (-39.245, 10.29) -> (-39.245, 11.29)
  line L44 (-41.645, 10.29) -> (-39.245, 10.29)
  line L45 (-41.645, 11.29) -> (-41.645, 10.29)
  line L46 (-39.245, 11.29) -> (-41.645, 11.29)
  line L47 (-37.34, 5.21) -> (-37.34, 6.21)
  line L48 (-39.74, 5.21) -> (-39.24, 5.21)
  line L49 (-39.74, 6.21) -> (-39.74, 5.21)
  line L50 (-37.34, 6.21) -> (-39.74, 6.21)
  line L51 (-3.05, 5.21) -> (-3.05, 6.21)
  line L52 (-5.45, 5.21) -> (-4.95, 5.21)
  line L53 (-5.45, 6.21) -> (-5.45, 5.21)
  line L54 (-3.05, 6.21) -> (-5.45, 6.21)
  line L55 (-6.86, 5.21) -> (-6.86, 6.21)
  line L56 (-9.26, 5.21) -> (-8.76, 5.21)
  line L57 (-9.26, 6.21) -> (-9.26, 5.21)
  line L58 (-6.86, 6.21) -> (-9.26, 6.21)
  line L59 (-10.67, 5.21) -> (-10.67, 6.21)
  line L60 (-13.07, 5.21) -> (-12.57, 5.21)
  line L61 (-13.07, 6.21) -> (-13.07, 5.21)
  line L62 (-10.67, 6.21) -> (-13.07, 6.21)
  line L63 (-30.215, 11.29) -> (-30.215, 10.29)
  line L64 (-27.815, 11.29) -> (-30.215, 11.29)
  line L65 (-27.815, 10.29) -> (-27.815, 11.29)
  line L66 (-30.215, 10.29) -> (-27.815, 10.29)
  line L67 (-18.785, 11.29) -> (-18.785, 10.29)
  line L68 (-16.385, 11.29) -> (-18.785, 11.29)
  line L69 (-16.385, 10.29) -> (-16.385, 11.29)
  line L70 (-18.785, 10.29) -> (-16.385, 10.29)
  line L71 (-14.975, 11.29) -> (-14.975, 10.29)
  line L72 (-12.575, 11.29) -> (-14.975, 11.29)
  line L73 (-12.575, 10.29) -> (-12.575, 11.29)
  line L74 (-14.975, 10.29) -> (-12.575, 10.29)
  line L75 (-34.025, 11.29) -> (-34.025, 10.29)
  line L76 (-31.625, 11.29) -> (-34.025, 11.29)
  line L77 (-31.625, 10.29) -> (-31.625, 11.29)
  line L78 (-34.025, 10.29) -> (-31.625, 10.29)
  line L79 (-25.91, 5.21) -> (-25.91, 6.21)
  line L80 (-28.31, 5.21) -> (-27.81, 5.21)
  line L81 (-28.31, 6.21) -> (-28.31, 5.21)
  line L82 (-25.91, 6.21) -> (-28.31, 6.21)
  line L83 (-18.29, 5.21) -> (-18.29, 6.21)
  line L84 (-20.69, 5.21) -> (-20.19, 5.21)
  line L85 (-20.69, 6.21) -> (-20.69, 5.21)
  line L86 (-18.29, 6.21) -> (-20.69, 6.21)
  line L87 (-33.53, 5.21) -> (-33.53, 6.21)
  line L88 (-35.93, 5.21) -> (-35.43, 5.21)
  line L89 (-35.93, 6.21) -> (-35.93, 5.21)
  line L90 (-33.53, 6.21) -> (-35.93, 6.21)
  line L91 (-41.15, 5.21) -> (-41.15, 6.21)
  line L92 (-43.55, 5.21) -> (-43.05, 5.21)
  line L93 (-43.55, 6.21) -> (-43.55, 5.21)
  line L94 (-41.15, 6.21) -> (-43.55, 6.21)
  line L95 (-14.48, 5.21) -> (-14.48, 6.21)
  line L96 (-16.88, 5.21) -> (-16.38, 5.21)
  line L97 (-16.88, 6.21) -> (-16.88, 5.21)
  line L98 (-14.48, 6.21) -> (-16.88, 6.21)
  line L99 (-37.835, 11.29) -> (-37.835, 10.29)
  line L100 (-35.435, 11.29) -> (-37.835, 11.29)
  line L101 (-35.435, 10.29) -> (-35.435, 11.29)
  line L102 (-37.835, 10.29) -> (-35.435, 10.29)
  line L103 (-7.355, 11.29) -> (-7.355, 10.29)
  line L104 (-4.955, 11.29) -> (-7.355, 11.29)
  line L105 (-4.955, 10.29) -> (-4.955, 11.29)
  line L106 (-7.355, 10.29) -> (-4.955, 10.29)
  line L107 (-29.72, 5.21) -> (-29.72, 6.21)
  line L108 (-32.12, 5.21) -> (-31.62, 5.21)
  line L109 (-32.12, 6.21) -> (-32.12, 5.21)
  line L110 (-29.72, 6.21) -> (-32.12, 6.21)
  line L111 (-22.1, 5.21) -> (-22.1, 6.21)
  line L112 (-24.5, 5.21) -> (-24, 5.21)
  line L113 (-24.5, 6.21) -> (-24.5, 5.21)
  line L114 (-22.1, 6.21) -> (-24.5, 6.21)
  line L115 (-39.345, 10.99) -> (-41.545, 10.99)
  line L116 (-39.345, 10.59) -> (-39.345, 10.99)
  line L117 (-41.545, 10.59) -> (-39.345, 10.59)
  line L118 (-41.545, 10.99) -> (-41.545, 10.59)
  line L119 (-41.65, 0) -> (-41.65, 5.21)
  line L120 (-39.24, 5.21) -> (-39.24, 0)
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  horizontal L115
  vertical L116
  horizontal L117
  vertical L118
  dimension "d88" distance L43 L116 = 0.1
  dimension "d89" distance L45 L118 = 0.1
  dimension "d90" distance L46 L115 = 0.3
  dimension "d91" distance L44 L117 = 0.3
extrude "Extrude11" new body sketch "Sketch15" profile of L115 L116 L117 L118 against normal blind 10 bodies "large_pin"
sketch "Sketch16" plane through (0, 0, 10.99) normal (0, 0, 1) x axis (-1, 0, 0)
  line L1 (-39.345, -10) -> (-41.545, -10)
  line L2 (-39.345, 0) -> (-39.345, -10)
  line L3 (-41.545, 0) -> (-39.345, 0)
  line L4 (-41.545, -10) -> (-41.545, 0)
  line L5 (-41.145, 0) -> (-39.745, 0)
  line L6 (-41.145, -7) -> (-41.145, 0)
  line L7 (-39.745, -7) -> (-41.145, -7)
  line L8 (-39.745, 0) -> (-39.745, -7)
  point P6 (-39.745, 0)
  point P9 (-39.745, -7)
  horizontal L5
  vertical L6
  horizontal L7
  vertical L8
  coincident L3 P6
  dimension "d94" distance P6 P9 = 7
  dimension "d95" distance L2 L8 = 0.4
  dimension "d96" distance L4 L6 = 0.4
extrude "Extrude12" cut sketch "Sketch16" profile of L3 L5 L6 L7 L8 no distance stored
sketch "Sketch17" plane through (0, 10, 0) normal (0, 1, 0) x axis (-1, 0, 0)
  line L1 (-39.345, 10.59) -> (-41.545, 10.59)
  line L2 (-39.345, 10.99) -> (-39.345, 10.59)
  line L3 (-41.545, 10.99) -> (-39.345, 10.99)
  line L4 (-41.545, 10.59) -> (-41.545, 10.99)
  line L5 (-39.345, 10.99) -> (-41.545, 10.99)
  line L6 (-39.345, -4.5) -> (-39.345, 10.99)
  line L7 (-41.545, -4.5) -> (-39.345, -4.5)
  line L8 (-41.545, 10.99) -> (-41.545, -4.5)
  line L9 (-40.445, 10.99) -> (-40.445, -4.5)
  line L10 (-40.045, 10.99) -> (-40.045, -4.5)
  line L11 (-40.845, 10.99) -> (-40.845, -4.5)
  line L12 (-41.545, 7.41) -> (-40.845, 6.71)
  line L13 (-39.8551, 6.71) -> (-40.845, 6.71)
  line L14 (-39.345, 7.41) -> (-40.045, 6.71)
  line L15 (-41.545, 4.01) -> (-40.845, 4.71)
  line L16 (-39.8551, 4.71) -> (-40.845, 4.71)
  line L17 (-39.345, 4.01) -> (-40.045, 4.71)
  line L18 (-41.545, 0.7) -> (-40.845, 0)
  line L19 (-39.345, 0.7) -> (-40.045, 0)
  line L20 (-39.645, -4.5) -> (-39.645, 10.99)
  line L21 (-41.245, 10.99) -> (-41.245, -4.5)
  line L22 (-40.045, -4.1) -> (-40.445, -4.5)
  line L23 (-39.8793, -4.5) -> (-40.445, -4.5)
  line L24 (-40.845, -4.1) -> (-40.445, -4.5)
  line L25 (-5.0797, 0) -> (-7.36, 0)
  line L26 (-8.76, 0) -> (-11.17, 0)
  line L27 (-12.57, 0) -> (-14.98, 0)
  line L28 (-16.38, 0) -> (-18.79, 0)
  line L29 (-20.19, 0) -> (-22.6, 0)
  line L30 (-24, 0) -> (-26.41, 0)
  line L31 (-27.81, 0) -> (-30.22, 0)
  line L32 (-31.62, 0) -> (-34.03, 0)
  line L33 (-35.43, 0) -> (-37.84, 0)
  line L34 (-39.24, 0) -> (-41.65, 0)
  line L35 (-43.55, 5.21) -> (-43.05, 5.21)
  line L36 (-43.05, 0) -> (-44.1, 0)
  line L37 (-41.65, 5.21) -> (-41.15, 5.21)
  line L38 (-40.2793, 10.99) -> (-40.845, 10.99)
  line L39 (-41.245, 10.19) -> (-40.845, 10.59)
  line L40 (-40.2793, 10.59) -> (-40.845, 10.59)
  line L41 (-39.645, 10.19) -> (-40.045, 10.59)
  point P5 (-41.545, 10.99)
  point P6 (-41.545, 10.99)
  point P10 (-40.445, -4.5)
  point P11 (-40.445, 10.99)
  point P16 (-40.845, 6.71)
  point P17 (-41.545, 7.41)
  point P19 (-40.045, 6.71)
  point P20 (-39.345, 7.41)
  point P22 (-40.845, 4.71)
  point P23 (-41.545, 4.01)
  point P25 (-40.045, 4.71)
  point P26 (-39.345, 4.01)
  point P27 (-40.845, 0)
  point P28 (-41.545, 0.7)
  point P29 (-40.045, 0)
  point P30 (-39.345, 0.7)
  point P35 (-40.045, -4.1)
  point P37 (-40.845, -4.1)
  point P65 (-40.845, 10.59)
  point P66 (-41.245, 10.19)
  point P68 (-40.045, 10.59)
  point P69 (-39.645, 10.19)
  point P21 (-41.15, 6.21)
  point P24 (-39.8551, 4.71)
  horizontal L5
  vertical L6
  horizontal L7
  vertical L8
  coincident P5 P6
  midpoint L7 P10
  midpoint L5 P11
  horizontal L13
  coincident L11 P16
  coincident L8 P17
  coincident L13 P19
  coincident L10 P19
  coincident L6 P20
  perpendicular L12 L14
  horizontal L16
  coincident L11 P22
  coincident L8 P23
  coincident L10 P25
  coincident L16 P25
  coincident L6 P26
  coincident L11 P27
  coincident L8 P28
  parallel L17 L18
  coincident L10 P29
  coincident L6 P30
  perpendicular L18 L19
  horizontal L23
  coincident L10 P35
  coincident L11 P37
  perpendicular L22 L24
  horizontal L38
  horizontal L40
  coincident L1 P65
  coincident L11 P65
  coincident L21 P66
  coincident L10 P68
  coincident L1 P68
  coincident L20 P69
  perpendicular L39 L41
  dimension "d99" = 0.4
  dimension "d100" = -0.4
  dimension "d101" angle L12 L13 = 135
  dimension "d102" distance P16 P21 = 0.5
  dimension "d103" angle L15 L16 = 135
  dimension "d104" distance P22 P24 = 0.9899
  dimension "d106" = 0.3
  dimension "d107" = 0.3
  dimension "d110" angle L22 L23 = 45
  dimension "d158" angle L39 L40 = 135
extrude "Extrude13" add sketch "Sketch17" profile of L1 L3 L5 L10 L11 L12 L14 L15 L17 L18 L19 L20 L21 L22 L24 L34 L39 L41 along normal blind 0.4
fillet "Fillet8" radius 0.2
rectangular_pattern "R-Pattern1" countU 10 uSpaceDistance -3.81 vSpaceDistance 0 bodies "large_pin (1)", "large_pin (2)", "large_pin (3)", "large_pin (4)", "large_pin (5)", "large_pin (6)", "large_pin (7)", "large_pin (8)"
